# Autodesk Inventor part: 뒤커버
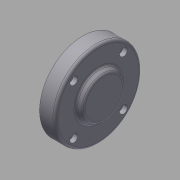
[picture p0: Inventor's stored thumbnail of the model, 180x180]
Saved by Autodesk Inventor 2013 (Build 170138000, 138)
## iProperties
Company: 한국ATC센터
Created: 2015-12
Part Number: 뒤커버
Document SubType Name: Modeling
Designer: mdu
Density: 2.71 g/cm^3
Mass: 105.756 g
Surface Area: 115.002 cm^2
Volume: 39.0244 cm^3
Material: 알루미늄 6061
Author: mdu
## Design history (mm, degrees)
sketch "스케치1"
  geometry: L1 (-10.5, 0)-(10.5, 0); L2 (10.5, 0)-(10.5, 22.5); L3 (10.5, 22.5)-(5.5, 22.5); L4 (5.5, 22.5)-(5.5, 32.5); L5 (5.5, 32.5)-(-6.5, 32.5); L6 (-6.5, 32.5)-(-6.5, 17.5); L7 (-6.5, 17.5)-(-10.5, 15.191); L8 (-10.5, 15.191)-(-10.5, 0); 2 further points
  constraints: 16 end point, 3 parallel, 3 perpendicular, 1 coincident, 1 horizontal, 1 midpoint
  dimensions: "d0" = 21 distance of L1.start L1.end; "d1" = 65 diameter of L5 L1; "d2" = 45 diameter of L3 L1; "d3" = 35 diameter of L6.end L1; "d4" = 120 deg angle of L7 L6; "d5" = 12 distance of L4.end L5.end; "d6" = 5 distance of L2.end L3.end
revolve "회전1" sketch "스케치1" stored, may be unused: angle "d7" = 90 deg
sketch "스케치2"
  geometry: L1 (0, 0)-(32.5, 0); L2 (0, 0)-(18.738, 18.738); 1 further point
  constraints: 4 end point, 1 horizontal, 1 horizontal alignment, 1 other
  dimensions: "d8" = 45 deg angle of L1 L2; "d9" = 26.5 distance of L1.start L2.end
hole "구멍1" sketch "스케치2" at (18.738, 18.738) diameter "d10" = 3.4; stored, may be unused: countersink angle "d14" = 90 deg, drill point angle "d16" = 118 deg; dims "d11" = 6, "d12" = 6, "d13" = 3.3, "d15" = 8
fillet "모깎기1" dims "d20" = 2
hole "구멍2" diameter "d23" = 15; stored, may be unused: countersink angle "d27" = 90 deg, drill point angle "d29" = 0 deg; dims "d21" = 10, "d22" = 10, "d24" = 6, "d25" = 35, "d26" = 11, "d28" = 14
chamfer "모따기1" distance "d39" = 1; stored, may be unused: second distance "d40" = 2, angle "d41" = 45 deg
fillet "모깎기2" dims "d42" = 0.3
chamfer "모따기3" distance "d57" = 1; stored, may be unused: second distance "d58" = 2, angle "d59" = 45 deg
fillet "모깎기4" dims "d60" = 1
node "솔리드1"
pattern_circular "원형 패턴1" dims angle "d18" = 360 deg
